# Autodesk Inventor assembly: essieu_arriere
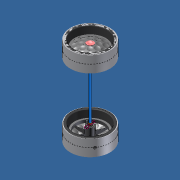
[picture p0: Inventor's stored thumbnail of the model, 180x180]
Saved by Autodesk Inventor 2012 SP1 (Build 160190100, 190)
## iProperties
Created: 2011-01
Part Number: essieu_arriere
Document SubType Name: Assembly
Designer: eric
Mass: 6204.37 g
Surface Area: 10780.2 cm^2
Volume: 6204.37 cm^3
Density: 1 g/cm^3
Author: eric
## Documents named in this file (5)
- I:\TSsi\EDT TDP\chariot_de_golf\chariot_de_golf_trolem\essieu_arriere.iam
- I:\TSsi\EDT TDP\chariot_de_golf\chariot_de_golf_trolem\62goupille_epingle_Defaut.ipt
- I:\TSsi\EDT TDP\chariot_de_golf\chariot_de_golf_trolem\montage7roue_caoutchouc_Defaut.iam
- I:\TSsi\EDT TDP\chariot_de_golf\chariot_de_golf_trolem\51axe_Defaut.ipt
- I:\TSsi\EDT TDP\chariot_de_golf\chariot_de_golf_trolem\12roue+axe_Defaut.iam
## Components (5 placed, 4 different names)
1. 12roue+axe_Defaut:1 [sub-assembly]
2. montage7roue_caoutchouc_Defaut:1 [sub-assembly]
3. montage7roue_caoutchouc_Defaut:2 [sub-assembly]
4. 51axe_Defaut:1
5. 62goupille_epingle_Defaut:1
